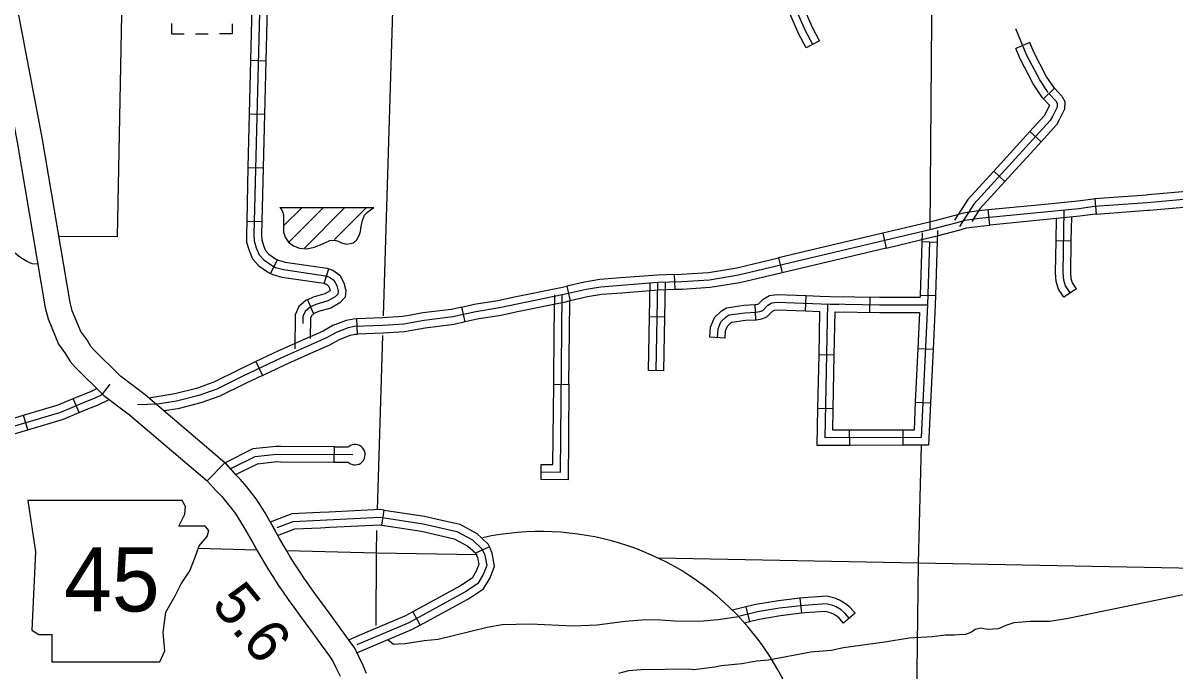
# Model space of a CAD drawing. Extents: x 1370567 to 1373900, y 377514 to 379648.
# Drawn here: x 1371737.8 to 1372062.3, y 378175.1 to 378357.5 of the extents above; entities that cross this region are included whole.
import ezdxf

# ---------------------------------------------------------------- set-up
doc = ezdxf.new("R2010")
doc.units = 0
doc.layers.add('Default', color=7, linetype='Continuous')

msp = doc.modelspace()

# ---------------------------------------------------------------- linework, layer by layer
at = {"layer": 'Default'}
for p, q in [((1371786.4, 378354.49), (1371789.97, 378354.48)), ((1371962.17, 378352.54), (1371958.4, 378350.5)), ((1372021.39, 378352), (1372017.43, 378350.37)), ((1371801.9, 378347.02), (1371806.19, 378346.92)), ((1372025.21, 378336.21), (1372028.34, 378339.14)), ((1371801.54, 378331.94), (1371805.82, 378331.84)), ((1372021.37, 378326.98), (1372024.54, 378324.09)), ((1371801.17, 378316.86), (1371805.45, 378316.76)), ((1372011.2, 378315.83), (1372014.37, 378312.95)), ((1372039.73, 378308), (1372040.04, 378303.73)), ((1371810.18, 378305.55), (1371836.58, 378305.55)), ((1371811.27, 378300.48), (1371816.24, 378305.45)), ((1371812.74, 378295.89), (1371822.26, 378305.42)), ((1371817.09, 378294.18), (1371828.37, 378305.46)), ((1371825.54, 378296.57), (1371834.38, 378305.41)), ((1372010.08, 378300.63), (1372009.66, 378304.89)), ((1371800.8, 378301.78), (1371805.09, 378301.67)), ((1371979.96, 378298.36), (1371980.95, 378294.19)), ((1371990.99, 378296.01), (1371995.27, 378295.87)), ((1372033.07, 378296.11), (1372028.78, 378296.19)), ((1371950.61, 378291.4), (1371951.59, 378287.23)), ((1371807.53, 378287.05), (1371809.45, 378290.88)), ((1371822.66, 378284.22), (1371823.91, 378288.32)), ((1371936.03, 378288.14), (1371936.03, 378288.14)), ((1371921.46, 378282.47), (1371921.31, 378286.75)), ((1371890.97, 378283.48), (1371891.92, 378279.3)), ((1372034.5, 378282.72), (1372030.94, 378280.35)), ((1371817.96, 378279.64), (1371819.65, 378275.7)), ((1371958.23, 378276.5), (1371958.38, 378280.78)), ((1371976.28, 378280.38), (1371976.2, 378276.09)), ((1371990.49, 378280.93), (1371994.77, 378280.79)), ((1371862.33, 378273.39), (1371861.4, 378277.57)), ((1371944.21, 378274), (1371943.98, 378278.28)), ((1371832.02, 378269.94), (1371831.86, 378274.23)), ((1371918.57, 378274.71), (1371914.28, 378274.79)), ((1371935.54, 378268.81), (1371931.27, 378269.1)), ((1371989.82, 378265.89), (1371994.11, 378265.69)), ((1371803.38, 378262.21), (1371805.21, 378258.34)), ((1371966.3, 378264.02), (1371962.02, 378264.1)), ((1371918.29, 378259.62), (1371914, 378259.7)), ((1371887.3, 378255.86), (1371891.58, 378255.81)), ((1371891.58, 378255.81), (1371891.58, 378255.81)), ((1371753.64, 378247.87), (1371751.96, 378251.81)), ((1371989.12, 378250.82), (1371993.4, 378250.62)), ((1371739.13, 378242.98), (1371737.91, 378247.09)), ((1371966, 378248.93), (1371961.71, 378249.02)), ((1371970.54, 378242.91), (1371970.55, 378238.62)), ((1371985.63, 378242.94), (1371985.64, 378238.66)), ((1371825.49, 378238.21), (1371810.4, 378238.33)), ((1371825.46, 378233.92), (1371825.49, 378238.21)), ((1371794.69, 378233.72), (1371789.64, 378228.63)), ((1371810.37, 378234.04), (1371825.46, 378233.92)), ((1371825.46, 378233.92), (1371825.46, 378233.92)), ((1371883.72, 378228.99), (1371883.74, 378233.28)), ((1371838.87, 378216.17), (1371839.52, 378220.41)), ((1371838.87, 378216.17), (1371838.87, 378216.17)), ((1371869.16, 378210.11), (1371865.26, 378208.33)), ((1371869.16, 378210.11), (1371869.16, 378210.11)), ((1371956.56, 378195.61), (1371957.06, 378191.36)), ((1371847.58, 378191.78), (1371849.64, 378188.02)), ((1371941.42, 378193.14), (1371942.45, 378188.98)), ((1371972.16, 378191.42), (1371968.93, 378188.6))]:
    msp.add_line(p, q, dxfattribs=at)
for points in [[(1371724.84, 378383.91), (1371725.68, 378379.24), (1371736.12, 378324.02), (1371744.06, 378277.36), (1371744.86, 378274.25), (1371747.78, 378267.16), (1371749.8, 378264.42), (1371751.12, 378262.27), (1371752.45, 378260.67), (1371760.56, 378252.67), (1371767.78, 378247.24), (1371789.64, 378228.63)], [(1371794.69, 378233.72), (1371772.24, 378252.82), (1371765.24, 378258.09), (1371757.72, 378265.51), (1371756.94, 378266.44), (1371755.73, 378268.41), (1371754.05, 378270.69), (1371751.65, 378276.51), (1371751.05, 378278.86), (1371743.15, 378325.29), (1371732.71, 378380.54), (1371731.87, 378385.2)], [(1371766.01, 378383.94), (1371764.34, 378297.3)], [(1371842.5, 378382.48), (1371839.25, 378275.13)], [(1371960.29, 378351.52), (1371958.23, 378355.33), (1371955.76, 378360.89), (1371953.7, 378368.3), (1371952.16, 378375.61), (1371951.85, 378383.07)], [(1371993.87, 378381.93), (1371993.22, 378299.58)], [(1371804.65, 378371.57), (1371802.86, 378298.02), (1371802.92, 378296.17), (1371803.5, 378294.21), (1371804.28, 378292.28), (1371805.64, 378290.82), (1371807.79, 378289.32), (1371808.94, 378288.74), (1371811.15, 378288.1), (1371822.96, 378286.37), (1371824.1, 378286.02), (1371825.35, 378285.1), (1371826.18, 378283.63), (1371826.52, 378282.07), (1371826.45, 378281.24), (1371825.72, 378280.45), (1371823.66, 378279.28), (1371820.28, 378278.3), (1371818.74, 378277.65), (1371817.25, 378276.36), (1371816.62, 378274.95), (1371816.59, 378272.94)], [(1371962.17, 378352.54), (1371960.15, 378356.27), (1371957.78, 378361.61), (1371956.58, 378365.96)], [(1371958.4, 378350.5), (1371956.31, 378354.38), (1371953.74, 378360.16), (1371952.45, 378364.82)], [(1371802.27, 378362.1), (1371801.9, 378347.02)], [(1371806.56, 378362), (1371806.19, 378346.92)], [(1371779.6, 378357.36), (1371779.59, 378354.5), (1371783.16, 378354.5)], [(1371796.74, 378357.33), (1371796.73, 378354.47), (1371793.16, 378354.48)], [(1372026.56, 378337.95), (1372024.17, 378341.5), (1372020.57, 378348.37), (1372017.47, 378355.88)], [(1372024.97, 378336.46), (1372022.32, 378340.41), (1372018.63, 378347.46), (1372017.43, 378350.37)], [(1372028.34, 378339.14), (1372026.01, 378342.6), (1372022.52, 378349.27), (1372021.39, 378352)], [(1371801.9, 378347.02), (1371801.54, 378331.94)], [(1371806.19, 378346.92), (1371805.82, 378331.84)], [(1372026.77, 378337.67), (1372028.67, 378335.65), (1372029.08, 378334.92), (1372029.04, 378333.83), (1372027.78, 378331.24), (1372027.14, 378330.12), (1372005.63, 378306.56), (1372001.58, 378300.2)], [(1372028.34, 378339.14), (1372030.41, 378336.93), (1372031.24, 378335.45), (1372031.17, 378333.3), (1372029.67, 378330.24), (1372028.89, 378328.85), (1372024.54, 378324.09)], [(1372024.97, 378336.46), (1372026.92, 378334.39), (1372026.92, 378334.36), (1372025.88, 378332.24), (1372025.4, 378331.38), (1372021.37, 378326.98)], [(1371801.54, 378331.94), (1371801.17, 378316.86)], [(1371805.82, 378331.84), (1371805.45, 378316.76)], [(1372021.37, 378326.98), (1372011.2, 378315.83)], [(1372024.54, 378324.09), (1372014.37, 378312.95)], [(1371801.17, 378316.86), (1371800.8, 378301.78)], [(1371805.45, 378316.76), (1371805.09, 378301.67)], [(1372011.2, 378315.83), (1372003.92, 378307.86), (1372000.21, 378302.05)], [(1372100, 378311.02), (1372054.45, 378306.94), (1372039.56, 378305.84), (1372035.17, 378305.25), (1372007.13, 378302.49), (1372003.06, 378301.93), (1372000.84, 378301.23), (1371993.22, 378299.3), (1371939.28, 378286.51), (1371931.14, 378285.16), (1371923.34, 378284.68), (1371916.61, 378284.44), (1371900.54, 378283.21), (1371896.38, 378282.51), (1371889.7, 378280.99), (1371871.97, 378277.33), (1371865.3, 378276.24), (1371858.84, 378274.81), (1371850.77, 378273.78), (1371845.02, 378272.76), (1371839.17, 378272.37), (1371831.15, 378272.05), (1371829.38, 378271.68), (1371826.01, 378270.39), (1371823.29, 378268.89), (1371810.62, 378263.26), (1371799.69, 378258.1), (1371792.41, 378254.43), (1371787.28, 378252.63), (1371781.02, 378251.06), (1371775.72, 378250.19), (1371770.01, 378250.03)], [(1372014.37, 378312.95), (1372007.34, 378305.25), (1372005.03, 378301.63)], [(1372039.73, 378308), (1372039.33, 378307.98), (1372034.92, 378307.38), (1372024.68, 378306.37)], [(1372054.74, 378309.12), (1372054.28, 378309.08), (1372039.73, 378308)], [(1372069.76, 378310.46), (1372054.74, 378309.12)], [(1371810.18, 378305.55), (1371810.55, 378305.13), (1371810.91, 378304.5), (1371811.14, 378303.56), (1371811.14, 378302.14), (1371811.18, 378300.28), (1371811.18, 378298.63), (1371811.66, 378297.25), (1371812.56, 378295.83), (1371813.98, 378294.8), (1371815.64, 378294.17), (1371817.65, 378293.97), (1371819.94, 378294.41), (1371822.58, 378295.59), (1371824.2, 378296.3), (1371825.58, 378296.42), (1371826.53, 378296.14), (1371827.47, 378295.67), (1371829.01, 378295.31), (1371830.79, 378295.63), (1371831.73, 378296.42), (1371832.52, 378297.72), (1371832.88, 378298.86), (1371833.08, 378300.2), (1371833.39, 378301.9), (1371833.94, 378303.44), (1371834.69, 378304.15), (1371835.64, 378304.9), (1371836.58, 378305.55)], [(1372009.66, 378304.89), (1372006.88, 378304.62), (1372002.59, 378304.03), (1372000.26, 378303.3), (1371994.6, 378301.86)], [(1372024.68, 378306.37), (1372009.66, 378304.89)], [(1372032.72, 378281.54), (1372031.41, 378283.5), (1372030.92, 378285.13), (1372030.76, 378287.25), (1372031.09, 378304.85)], [(1372040.04, 378303.73), (1372054.62, 378304.8), (1372055.12, 378304.85)], [(1372055.12, 378304.85), (1372070.14, 378306.19)], [(1371800.8, 378301.78), (1371800.71, 378298.01), (1371800.79, 378295.82), (1371801.47, 378293.5), (1371802.44, 378291.11), (1371804.23, 378289.2), (1371806.69, 378287.48), (1371807.53, 378287.05)], [(1371805.09, 378301.67), (1371805, 378298.03), (1371805.05, 378296.51), (1371805.52, 378294.92), (1371806.11, 378293.46), (1371807.06, 378292.45), (1371808.89, 378291.16), (1371809.45, 378290.88)], [(1371994.6, 378301.86), (1371992.71, 378301.38), (1371979.96, 378298.36)], [(1372025.1, 378302.11), (1372010.08, 378300.63)], [(1372040.04, 378303.73), (1372039.78, 378303.71), (1372035.42, 378303.12), (1372025.1, 378302.11)], [(1372028.78, 378296.19), (1372028.9, 378302.48)], [(1372033.07, 378296.11), (1372033.2, 378302.9)], [(1371741.97, 378289.64), (1371740.36, 378289.76), (1371738.83, 378290.41), (1371736.87, 378291.61), (1371734.26, 378293.79), (1371730.89, 378296.73), (1371729.69, 378298.58), (1371728.82, 378300.87)], [(1371979.96, 378298.36), (1371965.28, 378294.88)], [(1371991.07, 378298.49), (1371990.49, 378280.93)], [(1371995.38, 378299.15), (1371994.77, 378280.79)], [(1371995.66, 378297.71), (1372001.43, 378299.17), (1372003.53, 378299.83), (1372007.38, 378300.36), (1372010.08, 378300.63)], [(1371764.34, 378297.3), (1371748.05, 378297.4)], [(1371965.28, 378294.88), (1371950.61, 378291.4)], [(1371993.13, 378295.94), (1371992.54, 378278.2), (1371990.8, 378240.81), (1371963.69, 378240.75), (1371964.45, 378278.44), (1371979.03, 378278.19), (1371992.54, 378278.2)], [(1371980.95, 378294.19), (1371993.73, 378297.22), (1371995.66, 378297.71)], [(1372030.94, 378280.35), (1372029.45, 378282.57), (1372028.8, 378284.74), (1372028.61, 378287.19), (1372028.78, 378296.19)], [(1372034.5, 378282.72), (1372033.37, 378284.42), (1372033.04, 378285.52), (1372032.9, 378287.32), (1372033.07, 378296.11)], [(1371936.03, 378288.14), (1371938.86, 378288.61), (1371950.61, 378291.4)], [(1371980.95, 378294.19), (1371966.27, 378290.71)], [(1371809.45, 378290.88), (1371809.73, 378290.74), (1371811.61, 378290.2), (1371823.43, 378288.47), (1371823.91, 378288.32)], [(1371823.91, 378288.32), (1371825.08, 378287.96), (1371826.99, 378286.55), (1371828.2, 378284.4), (1371828.68, 378282.21), (1371828.52, 378280.32), (1371827.07, 378278.76), (1371824.5, 378277.29), (1371821, 378276.28), (1371819.65, 378275.7)], [(1371921.31, 378286.75), (1371923.24, 378286.82), (1371930.89, 378287.29), (1371936.03, 378288.14)], [(1371966.27, 378290.71), (1371951.59, 378287.23)], [(1371807.53, 378287.05), (1371808.15, 378286.74), (1371810.69, 378286), (1371822.49, 378284.27), (1371822.66, 378284.22)], [(1371906.17, 378285.79), (1371900.28, 378285.34), (1371895.97, 378284.61), (1371890.97, 378283.48)], [(1371921.31, 378286.75), (1371916.49, 378286.58), (1371906.17, 378285.79)], [(1371951.59, 378287.23), (1371939.7, 378284.41), (1371936.73, 378283.91)], [(1371822.66, 378284.22), (1371823.13, 378284.08), (1371823.71, 378283.65), (1371824.15, 378282.86), (1371824.32, 378282.12), (1371822.82, 378281.26), (1371819.55, 378280.32), (1371817.96, 378279.64)], [(1371876.25, 378280.4), (1371889.24, 378283.08), (1371890.97, 378283.48)], [(1371921.46, 378282.47), (1371916.73, 378282.3), (1371906.49, 378281.52)], [(1371914.28, 378274.79), (1371914.46, 378284.48)], [(1371916.15, 378259.66), (1371916.61, 378284.44)], [(1371918.57, 378274.71), (1371918.75, 378284.4)], [(1371936.73, 378283.91), (1371931.38, 378283.03), (1371923.45, 378282.54), (1371921.46, 378282.47)], [(1371817.96, 378279.64), (1371817.6, 378279.49), (1371815.49, 378277.68), (1371814.49, 378275.42), (1371814.35, 378265.83)], [(1371861.4, 378277.57), (1371864.89, 378278.34), (1371871.58, 378279.44), (1371876.25, 378280.4)], [(1371891.92, 378279.3), (1371890.15, 378278.89), (1371877.11, 378276.2)], [(1371883.73, 378231.14), (1371889.19, 378231.12), (1371889.7, 378280.99)], [(1371887.45, 378270.94), (1371887.56, 378281.01)], [(1371891.74, 378270.9), (1371891.82, 378279.27)], [(1371906.49, 378281.52), (1371900.8, 378281.08), (1371896.8, 378280.41), (1371891.92, 378279.3)], [(1371933.4, 378268.96), (1371933.57, 378271.41), (1371934.38, 378273.37), (1371935.85, 378274.84), (1371936.67, 378275.33), (1371941.08, 378275.98), (1371944.18, 378276.14), (1371945.32, 378276.31), (1371946.14, 378276.63), (1371947.61, 378278.1), (1371948.75, 378278.76), (1371950.22, 378278.92), (1371967.61, 378278.31)], [(1371943.97, 378278.28), (1371944.77, 378278.39), (1371944.93, 378278.46), (1371946.3, 378279.82), (1371948.07, 378280.84), (1371950.14, 378281.07), (1371958.38, 378280.78)], [(1371958.41, 378280.78), (1371962.35, 378280.62), (1371965.19, 378280.57)], [(1371965.19, 378280.57), (1371979.05, 378280.33), (1371980.24, 378280.33)], [(1371980.24, 378280.33), (1371990.47, 378280.34)], [(1371990.49, 378280.93), (1371990.47, 378280.34)], [(1371994.77, 378280.79), (1371994.68, 378278.12), (1371994.11, 378265.69)], [(1371819.89, 378275.81), (1371819.01, 378275.05), (1371818.76, 378274.48), (1371818.68, 378268.71)], [(1371846.6, 378275.22), (1371844.76, 378274.89), (1371839.06, 378274.51), (1371831.86, 378274.23)], [(1371861.4, 378277.57), (1371858.47, 378276.92), (1371850.45, 378275.9), (1371846.6, 378275.22)], [(1371877.11, 378276.2), (1371872.36, 378275.22), (1371865.7, 378274.13), (1371862.33, 378273.39)], [(1371931.27, 378269.1), (1371931.45, 378271.9), (1371932.57, 378274.58), (1371934.52, 378276.54), (1371935.93, 378277.38), (1371940.86, 378278.11), (1371943.98, 378278.28)], [(1371944.21, 378274), (1371944.39, 378274.01), (1371945.88, 378274.22), (1371947.34, 378274.81), (1371948.92, 378276.39), (1371949.43, 378276.68), (1371950.3, 378276.77), (1371958.23, 378276.5)], [(1371958.23, 378276.5), (1371962.27, 378276.33)], [(1371962.02, 378264.1), (1371962.27, 378276.33)], [(1371966.3, 378264.02), (1371966.55, 378276.26)], [(1371966.55, 378276.26), (1371979.01, 378276.04), (1371980.24, 378276.05)], [(1371980.24, 378276.05), (1371990.3, 378276.06)], [(1371990.3, 378276.06), (1371989.82, 378265.89)], [(1371831.86, 378274.23), (1371830.88, 378274.19), (1371828.78, 378273.74), (1371825.1, 378272.34), (1371822.34, 378270.81), (1371817.15, 378268.5)], [(1371862.33, 378273.39), (1371859.21, 378272.7), (1371851.1, 378271.66), (1371847.35, 378271)], [(1371914, 378259.7), (1371914.28, 378274.79)], [(1371918.29, 378259.62), (1371918.57, 378274.71)], [(1371935.54, 378268.81), (1371935.68, 378270.91), (1371936.2, 378272.15), (1371937.18, 378273.13), (1371937.41, 378273.27), (1371941.29, 378273.85), (1371944.21, 378274)], [(1371818.89, 378264.59), (1371824.25, 378266.97), (1371826.91, 378268.44), (1371829.99, 378269.62), (1371831.41, 378269.92), (1371832.02, 378269.94)], [(1371847.35, 378271), (1371845.28, 378270.63), (1371839.28, 378270.23), (1371832.02, 378269.94)], [(1371839.08, 378269.54), (1371837.58, 378220.52)], [(1371887.3, 378255.86), (1371887.45, 378270.94)], [(1371891.58, 378255.81), (1371891.74, 378270.9)], [(1371817.15, 378268.5), (1371809.73, 378265.21), (1371803.38, 378262.21)], [(1371989.82, 378265.89), (1371989.12, 378250.82)], [(1371994.11, 378265.69), (1371993.4, 378250.62)], [(1371803.38, 378262.21), (1371798.75, 378260.03), (1371791.57, 378256.41), (1371789.97, 378255.84)], [(1371805.21, 378258.34), (1371811.52, 378261.32), (1371818.89, 378264.59)], [(1371961.71, 378249.02), (1371962.02, 378264.1)], [(1371966, 378248.93), (1371966.3, 378264.02)], [(1371731.99, 378243.09), (1371748.45, 378247.99), (1371755.31, 378250.91), (1371757.95, 378251.9), (1371759.93, 378252.9), (1371760.49, 378253.43), (1371762.39, 378255.89)], [(1371789.97, 378255.84), (1371786.66, 378254.68), (1371780.59, 378253.16), (1371773.25, 378251.96)], [(1371805.21, 378258.34), (1371800.63, 378256.18), (1371793.26, 378252.46), (1371791.39, 378251.8)], [(1371887.14, 378240.77), (1371887.3, 378255.86)], [(1371891.58, 378255.81), (1371891.43, 378240.73)], [(1371751.96, 378251.81), (1371754.51, 378252.9), (1371757.08, 378253.86), (1371758.58, 378254.62)], [(1371737.91, 378247.09), (1371747.72, 378250), (1371751.96, 378251.81)], [(1371753.64, 378247.87), (1371756.1, 378248.92), (1371758.81, 378249.93), (1371762.03, 378251.57)], [(1371791.39, 378251.8), (1371787.89, 378250.57), (1371781.45, 378248.96), (1371777.53, 378248.32)], [(1371989.12, 378250.82), (1371988.76, 378242.95), (1371985.63, 378242.94)], [(1371993.4, 378250.62), (1371992.85, 378238.68), (1371985.64, 378238.66)], [(1371723.52, 378243.85), (1371727.77, 378244.48), (1371731.49, 378245.18), (1371737.91, 378247.09)], [(1371739.13, 378242.98), (1371749.17, 378245.97), (1371753.64, 378247.87)], [(1371970.55, 378238.62), (1371961.5, 378238.6), (1371961.71, 378249.02)], [(1371970.54, 378242.91), (1371965.88, 378242.9), (1371966, 378248.93)], [(1371724.15, 378239.61), (1371728.48, 378240.25), (1371732.5, 378241.01), (1371739.13, 378242.98)], [(1371985.63, 378242.94), (1371970.54, 378242.91)], [(1371891.43, 378240.73), (1371891.31, 378228.97), (1371883.72, 378228.99)], [(1371883.74, 378233.28), (1371887.07, 378233.27), (1371887.14, 378240.77)], [(1371810.4, 378238.33), (1371809.11, 378238.34), (1371802.57, 378237.61), (1371794.72, 378233.68)], [(1371796.17, 378232.01), (1371803.18, 378235.52), (1371809.22, 378236.19), (1371830.68, 378236.02)], [(1371825.49, 378238.21), (1371829.46, 378238.18)], [(1371985.64, 378238.66), (1371970.55, 378238.62)], [(1371990.75, 378238.67), (1371989.89, 378205.51), (1371988.86, 378121.7)], [(1371831.23, 378181.52), (1371829.98, 378183.36), (1371827.55, 378186.71), (1371824.62, 378190.73), (1371821.41, 378195.04), (1371819.84, 378197.25), (1371818.28, 378199.39), (1371816.94, 378201.33), (1371815.64, 378203.2), (1371814.39, 378205.2), (1371813.08, 378207.27), (1371811.96, 378209.18), (1371810, 378212.37), (1371808.71, 378214.8), (1371805.96, 378219.62), (1371803.43, 378223.55), (1371802.19, 378225.23), (1371800.81, 378226.96), (1371799.03, 378229.02), (1371797.38, 378230.72), (1371794.69, 378233.72), (1371789.64, 378228.63)], [(1371794.72, 378233.68), (1371797.38, 378230.72), (1371797.71, 378230.39)], [(1371797.71, 378230.39), (1371803.8, 378233.43), (1371809.33, 378234.05), (1371810.37, 378234.04)], [(1371825.46, 378233.92), (1371829.42, 378233.89)], [(1371789.64, 378228.63), (1371792.17, 378225.84), (1371793.76, 378224.2), (1371795.32, 378222.39), (1371796.52, 378220.88), (1371797.54, 378219.5), (1371799.85, 378215.91), (1371802.45, 378211.35), (1371803.8, 378208.82), (1371805.84, 378205.51), (1371806.98, 378203.56), (1371808.34, 378201.4), (1371809.68, 378199.26), (1371811.07, 378197.27), (1371812.45, 378195.26), (1371814.04, 378193.07), (1371815.63, 378190.84), (1371818.87, 378186.49), (1371821.77, 378182.51), (1371824.13, 378179.26), (1371825.17, 378177.72)], [(1371839.52, 378220.41), (1371838.51, 378220.56), (1371824.03, 378219.84)], [(1371839.52, 378220.41), (1371850.87, 378218.67), (1371854.54, 378217.84)], [(1371824.03, 378219.84), (1371821.36, 378219.71), (1371813.47, 378219.36), (1371807.42, 378217.05)], [(1371807.42, 378217.05), (1371808.71, 378214.8), (1371809.52, 378213.27), (1371814.36, 378215.11), (1371821.56, 378215.43), (1371824.24, 378215.56)], [(1371809.38, 378215.51), (1371813.92, 378217.24), (1371821.46, 378217.57), (1371838.4, 378218.41), (1371850.47, 378216.57), (1371860.03, 378214.38), (1371864.39, 378212.04), (1371867.07, 378209.52), (1371867.91, 378207.68), (1371868.42, 378204.82), (1371867.41, 378202.31), (1371865.9, 378199.79), (1371862.71, 378197.61), (1371846.45, 378188.72), (1371831.86, 378182.51)], [(1371854.54, 378217.84), (1371860.79, 378216.41), (1371865.65, 378213.79), (1371868.85, 378210.79), (1371869.16, 378210.11)], [(1371824.24, 378215.56), (1371838.29, 378216.26), (1371838.87, 378216.17)], [(1371837.41, 378214.64), (1371837.23, 378208.29), (1371837.15, 378187.95)], [(1371838.87, 378216.17), (1371850.07, 378214.46), (1371853.58, 378213.66)], [(1371853.58, 378213.66), (1371859.27, 378212.36), (1371863.13, 378210.28), (1371865.3, 378208.25), (1371865.26, 378208.33)], [(1371803.61, 378209.17), (1371787.18, 378209.61)], [(1371865.75, 378207.82), (1371837.23, 378208.29), (1371812.1, 378208.95)], [(1371865.26, 378208.33), (1371865.85, 378207.04), (1371866.2, 378205.05), (1371865.48, 378203.26), (1371864.3, 378201.29), (1371861.59, 378199.44), (1371860.82, 378199.02)], [(1371862.87, 378195.26), (1371863.84, 378195.78), (1371867.5, 378198.29), (1371869.34, 378201.35), (1371870.63, 378204.59), (1371869.98, 378208.31), (1371869.16, 378210.11)], [(1372141.72, 378202.54), (1371989.89, 378205.51), (1371916.75, 378206.87)], [(1371860.82, 378199.02), (1371847.58, 378191.78)], [(1372075.48, 378198.8), (1372032.15, 378189.88), (1372026.97, 378189.07), (1372021.66, 378189.01), (1372016.91, 378188.72), (1372014.65, 378187.88), (1372012.44, 378186.96), (1372009.47, 378186.76), (1372007.46, 378187.18), (1372006.01, 378186.81), (1372005.22, 378186.2), (1372004.32, 378185.72), (1372003.29, 378185.39), (1372001.35, 378185.27), (1372000.2, 378185.22), (1371999.62, 378185.16), (1371997.59, 378185.16), (1371993.92, 378184.75), (1371987.41, 378184.34), (1371980.53, 378183.21), (1371968.88, 378181.6), (1371965.46, 378180.88), (1371959.73, 378180.38), (1371947.77, 378178.2), (1371944.4, 378177.88), (1371940.3, 378177.12), (1371934.48, 378176.59), (1371932.69, 378176.18), (1371926.73, 378175.45), (1371925.3, 378175.59), (1371911.91, 378175.41), (1371908.37, 378175.2), (1371905.55, 378174.41)], [(1371849.64, 378188.02), (1371862.87, 378195.26)], [(1371970.54, 378190.01), (1371969.32, 378191.41), (1371968.24, 378192.31), (1371966.83, 378193.17), (1371965.85, 378193.58), (1371963.98, 378194), (1371957.82, 378193.6), (1371950.86, 378192.79), (1371944.68, 378191.74), (1371939.36, 378190.42)], [(1371956.56, 378195.61), (1371950.56, 378194.91), (1371944.24, 378193.84), (1371941.42, 378193.14)], [(1371972.16, 378191.42), (1371970.82, 378192.95), (1371969.49, 378194.06), (1371967.8, 378195.08), (1371966.5, 378195.63), (1371964.16, 378196.16), (1371957.63, 378195.74), (1371956.56, 378195.61)], [(1371847.58, 378191.78), (1371845.51, 378190.65), (1371833.99, 378185.75)], [(1371941.42, 378193.14), (1371937.62, 378192.2)], [(1371957.06, 378191.36), (1371951.17, 378190.67), (1371945.12, 378189.64), (1371942.45, 378188.98)], [(1371968.93, 378188.6), (1371967.81, 378189.88), (1371967, 378190.56), (1371965.85, 378191.25), (1371965.19, 378191.53), (1371963.81, 378191.84), (1371958.01, 378191.47), (1371957.06, 378191.36)], [(1371849.64, 378188.02), (1371847.38, 378186.79), (1371835.67, 378181.81)], [(1371840.64, 378183.92), (1371842.19, 378182.64), (1371843.51, 378182.77), (1371845.47, 378182.87), (1371850.77, 378183.71), (1371854.76, 378184.12), (1371868.5, 378187.48), (1371872.72, 378188.18), (1371880.66, 378188.44), (1371892.72, 378187.86), (1371899.55, 378188.1), (1371907.39, 378189.15), (1371913.21, 378189.63), (1371917.47, 378189.54), (1371921.36, 378189.26), (1371928.39, 378189.13), (1371933.46, 378189.62), (1371939.36, 378190.42)], [(1371942.45, 378188.98), (1371941.01, 378188.62)], [(1371833.99, 378185.75), (1371829.62, 378183.89)], [(1371834.57, 378174.4), (1371834.03, 378175.74), (1371833.63, 378176.65), (1371831.23, 378181.52)], [(1371835.67, 378181.81), (1371831.88, 378180.19)], [(1371825.17, 378177.72), (1371825.93, 378176.11), (1371827.15, 378173.63)]]:
    msp.add_lwpolyline(points, dxfattribs=at)
msp.add_lwpolyline([(1371739.12, 378223.14), (1371741.29, 378208.64), (1371740.33, 378186.64), (1371742.26, 378185.43), (1371745.89, 378185.43), (1371745.89, 378177.7), (1371776.34, 378177.7), (1371777.79, 378180.84), (1371777.3, 378185.92), (1371778.03, 378191.72), (1371780.69, 378196.31), (1371782.38, 378199.69), (1371784.8, 378203.32), (1371786.25, 378207.19), (1371787.45, 378210.33), (1371789.63, 378212.99), (1371790.11, 378214.68), (1371789.15, 378215.89), (1371781.65, 378215.89), (1371783.35, 378219.27), (1371783.59, 378221.44), (1371782.59, 378223.12)], close=True, dxfattribs=at)
for centre, radius, start, end in [((1371831.33, 378236.01), 2.86, 228.009, 128.5301), ((1371883.64, 378137.62), 76.76, 346.0467, 102.2496)]:
    msp.add_arc(centre, radius, start, end, dxfattribs=at)

# ---------------------------------------------------------------- texts
msp.add_text('45', height=18.103, dxfattribs=at).set_placement((1371749.36, 378191.87))
msp.add_text('5.6', height=12.069, rotation=309.4237, dxfattribs=at).set_placement((1371790.58, 378193.71))

doc.saveas('drawing.dxf')
